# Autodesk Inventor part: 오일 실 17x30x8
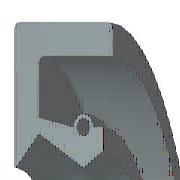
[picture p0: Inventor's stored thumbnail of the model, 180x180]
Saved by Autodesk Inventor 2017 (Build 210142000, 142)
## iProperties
IsCustomPart: 1
Created: 2012-02
Part Number: 오일 실 17x30x8
Material: 고무
Description: 오일-실
Document SubType Name: Modeling
Standard: KS B 2804
Designer: mduedu
Standards Organization: KS
Language: ko-KR
Size Designation: D - 17 30 8
Categories: <MemberInstance><Categories><Category DisplayName="샤프트 부품" InternalName="7f7aeb1f-a693-4053-b835-cee3144e0d98" Mnemonic="SHFT"><Category DisplayName="실링" Intern
Density: 0.93 g/cm^3
Appearance: 고무 - 검은색 - 버전 1.1
Author: mduedu
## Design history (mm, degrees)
revolve "본체" stored, may be unused: angle "d17" = 90 deg
revolve "스프링1" stored, may be unused: angle "d18" = 90 deg
body "Solid1"
sketch "스케치1"
  geometry: L1 (0, 15)-(8, 15); L2 (8, 13.25)-(1.75, 13.25); L3 (1.75, 10.25)-(4.9, 8.5); L4 (4.9, 8.5)-(0, 8.5); L5 (0, 0)-(9.586, 0) reference; L6 (4.9, 8.5)-(6.3, 9.375); L7 (0, 18)-(0, -3) reference; L8 (-1.941, 0)-(11.507, 0) reference; L9 (4.2, 10.6)-(1.75, 11.21); L10 (1.75, 11.21)-(1.75, 13.25); L11 (0, 15)-(0, 8.588); L12 (4.9, 8.5)-(0, 8.5); L13 (1.75, 10.25)-(0.152, 8.528); L14 (8, 15)-(8, 13.25); L15 (5.6, 10.6)-(6.3, 10.6); L16 (6.3, 10.6)-(6.3, 9.375); C1 r 0.455 at (4.9, 10.6); A1 r 0.7 centre (4.9, 10.6) between (5.6, 10.6) and (4.2, 10.6); A2 r 0.088 centre (0.088, 8.588) between (0, 8.588) and (0.152, 8.528); 1 further point
  constraints: 28 end point, 5 horizontal alignment, 5 point on line, 4 point on circle, 4 vertical alignment, 3 centre point, 3 tangent, 2 collinear, 2 horizontal, 2 perpendicular, 1 coincident, 1 parallel
  dimensions: "d0" = 30 diameter of L1 L5 (= SD2); "d1" = 1.75 distance of L1.end L2.start (= SD); "d2" = 0.91 diameter of C1 (= SPDI); "d3" = 1.4 diameter of A1 (= SPDA); "d4" = 17 diameter of L3.end L5 (= NND); "d5" = 20.5 diameter of L3.start L5 (= TKDM); "d7" = 22.42 diameter of L9.end L5 (= TKDM + 0.24 x SWDT); "d8" = 1.75 distance between parallel lines of L11 L10 (= SD); "d9" = 4.9 distance from line of L11 C1.centre (= SPDST); "d10" = 21.2 diameter of C1.centre L5 (= HLDM); "d11" = 0.0875 radius of A2 (= 0.25 x LAB); "d12" = 6.3 distance between parallel lines of L11 L16 (= SDI); "d13" = 18.75 diameter of L6.end L5 (= ABDM); "d14" = 8 distance from line of L11 L1.end (= SWDT)
fillet "모깎기1" dims "d6" = 0.3 (= RR)
other parameters: "SD2" = 30 [user parameter; used in 1 equation term], "SWDT" = 8 [user parameter; used in 2 equation terms], "RR" = 0.3 [user parameter; used in 1 equation term], "SD" = 1.75 [user parameter; used in 2 equation terms], "NND" = 17 [user parameter; used in 1 equation term], "SPDA" = 1.4 [user parameter; used in 1 equation term], "SPDI" = 0.91 [user parameter; used in 1 equation term], "TKDM" = 20.5 [user parameter; used in 2 equation terms], "HLDM" = 21.2 [user parameter; used in 1 equation term], "ABDM" = 18.75 [user parameter; used in 1 equation term], "SDI" = 6.3 [user parameter; used in 1 equation term], "SPDST" = 4.9 [user parameter; used in 1 equation term], "LAB" = 0.35 [user parameter; used in 1 equation term], "d15" = 0, "d16" = 0, "d19" = 0
